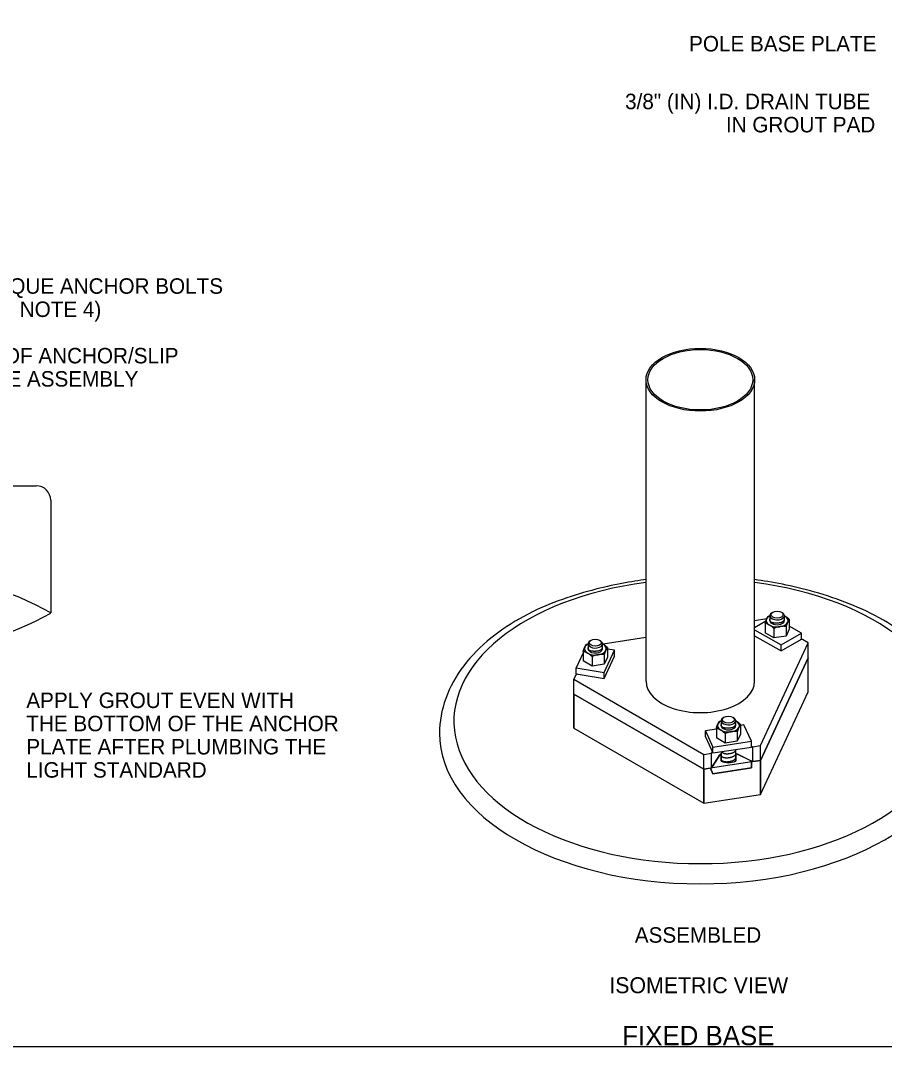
# Model space of a CAD drawing. Extents: x 99862 to 104211, y 98939 to 102076.
# Drawn here: x 101332 to 102226, y 100000 to 101060 of the extents above; entities that cross this region are included whole.
import ezdxf

# ---------------------------------------------------------------- set-up
doc = ezdxf.new("R2010")
doc.units = 0
for name, color, linetype in [('Level 1', 7, 'Continuous'), ('Level 11', 7, 'Continuous'), ('Level 12', 7, 'Continuous'), ('Level 2', 7, 'Continuous'), ('Level 20', 7, 'Continuous'), ('Level 62', 7, 'Continuous'), ('Level 7', 7, 'Continuous'), ('Level 8', 7, 'Continuous'), ('Level 9', 7, 'Continuous')]:
    doc.layers.add(name, color=color, linetype=linetype)

msp = doc.modelspace()

# ---------------------------------------------------------------- linework, layer by layer
at = {"layer": 'Level 1'}
msp.add_lwpolyline([(99862, 99999.5), (103151, 99999.5), (103151, 102075.5), (99862, 102075.5)], close=True, dxfattribs=at)
for centre, start, end in [((101228.7, 100214), 60, 120), ((101228.7, 100681.6), 240, 300)]:
    msp.add_arc(centre, 270, start, end, dxfattribs=at)
at = {"layer": 'Level 11'}
for p, q in [((102103.6, 100439.2), (102092.1, 100432.6)), ((102140.6, 100426.9), (102128, 100434.2)), ((102092.1, 100430.4), (102119.4, 100414.7)), ((102092.1, 100424.3), (102119.4, 100408.6)), ((102119.4, 100414.7), (102140.6, 100426.9)), ((102140.6, 100420.8), (102140.6, 100426.9)), ((102119.4, 100408.6), (102140.6, 100420.8)), ((102119.4, 100408.6), (102119.4, 100414.7)), ((101914.7, 100406.5), (101907.4, 100390.9)), ((101936.4, 100386.4), (101947.1, 100409.4)), ((101936.4, 100380.2), (101947.1, 100403.3)), ((101947.1, 100409.4), (101939.8, 100410.5)), ((101947.1, 100403.3), (101947.1, 100409.4)), ((101907.4, 100384.7), (101907.4, 100390.9)), ((101907.4, 100390.9), (101936.4, 100386.4)), ((101907.4, 100384.7), (101936.4, 100380.2)), ((101936.4, 100380.2), (101936.4, 100386.4)), ((102052.5, 100327.6), (102041.2, 100325.8)), ((102081, 100332), (102077.6, 100331.5)), ((102088.8, 100315.3), (102081, 100332)), ((102041.2, 100319.7), (102041.2, 100325.8)), ((102041.2, 100325.8), (102049, 100309.1)), ((102041.2, 100319.7), (102049, 100303)), ((102049, 100309.1), (102088.8, 100315.3)), ((102049, 100303), (102088.8, 100309.2)), ((102049, 100303), (102049, 100309.1)), ((102088.8, 100309.2), (102088.8, 100315.3))]:
    msp.add_line(p, q, dxfattribs=at)
at = {"layer": 'Level 12'}
for centre, major_axis, start_param, end_param in [((102035.9, 100335.8), (-255, 0), 4.934807, 10.773157), ((102035.9, 100323.6), (-270, 0), 6.283185, 9.424762)]:
    msp.add_ellipse(centre, major_axis=major_axis, ratio=0.57735, start_param=start_param, end_param=end_param, dxfattribs=at)
for points in [[(101979.6, 100482.3), (101965.9, 100480.6), (101925.7, 100473.6), (101852.3, 100448.7), (101784.3, 100397), (101765.9, 100347.3), (101765.9, 100323.6)], [(102305.9, 100323.6), (102305.9, 100345.1), (102289.9, 100392.8), (102227.3, 100444.3), (102152.7, 100472), (102109.3, 100480.1), (102092.1, 100482.3)]]:
    msp.add_open_spline(points, degree=3, dxfattribs=at)
at = {"layer": 'Level 2'}
for p, q in [((102147.5, 100366.3), (102147.5, 100401.5)), ((102147.5, 100366.3), (102147.5, 100401.5)), ((101904.9, 100328.8), (101904.9, 100364)), ((101904.9, 100328.8), (101904.9, 100364)), ((102098.2, 100260.1), (102147.5, 100366.3)), ((101904.9, 100328.8), (102039.6, 100251)), ((102098.2, 100295.3), (102039.6, 100286.2)), ((102054.4, 100298.2), (102047.6, 100287.5)), ((102056.2, 100301), (102054.4, 100298.2)), ((102057.5, 100294.7), (102057.5, 100302.4)), ((102072.5, 100302.6), (102072.5, 100294.7)), ((102088.8, 100293.9), (102088.3, 100295)), ((102098.2, 100260.1), (102098.2, 100295.3)), ((102098.2, 100260.1), (102098.2, 100295.3)), ((102039.6, 100251), (102039.6, 100286.2)), ((102039.6, 100251), (102039.6, 100286.2)), ((102047.6, 100287.5), (102046.3, 100287.3)), ((102046.3, 100287.3), (102049, 100281.6)), ((102049, 100281.6), (102088.8, 100287.7)), ((102088.8, 100287.7), (102088.8, 100293.9)), ((102039.6, 100251), (102098.2, 100260.1))]:
    msp.add_line(p, q, dxfattribs=at)
for points in [[(102098.2, 100260.1), (102147.5, 100366.3), (102147.5, 100401.5), (102098.2, 100295.3), (102098.2, 100260.1)], [(101904.9, 100328.8), (102039.6, 100251), (102039.6, 100286.2), (101904.9, 100364), (101904.9, 100328.8)], [(102046.3, 100287.3), (102039.6, 100286.2), (102039.6, 100251), (102098.2, 100260.1), (102098.2, 100295.3), (102090.2, 100294.1), (102088.3, 100295), (102088.8, 100293.9), (102088.8, 100287.7), (102049, 100281.6), (102046.3, 100287.3)], [(102088.3, 100295), (102075, 100301.4), (102072.5, 100302.6)]]:
    msp.add_lwpolyline(points, dxfattribs=at)
for major_axis, start_param, end_param in [((-9.38, 0), 5.639684, 5.931236), ((10.7, 0), 3.935758, 5.48902)]:
    msp.add_ellipse((102065, 100299.1), major_axis=major_axis, ratio=0.57735, start_param=start_param, end_param=end_param, dxfattribs=at)
at = {"layer": 'Level 62'}
for points, degree in [([(102122.7, 100441.1), (102121.9, 100438.7), (102118.9, 100437.4), (102115.4, 100437.2), (102111, 100437.1), (102107.6, 100438.7), (102107.9, 100441.3)], 4), ([(101934.5, 100412), (101933.7, 100409.6), (101930.7, 100408.2), (101927.2, 100408.1), (101922.8, 100408), (101919.4, 100409.6), (101919.7, 100412.2)], 4), ([(102072.3, 100332.4), (102071.5, 100330.1), (102068.5, 100328.7), (102065, 100328.6), (102060.6, 100328.4), (102057.2, 100330.1), (102057.5, 100332.6)], 4), ([(102072.3, 100305.9), (102071.6, 100304), (102069.5, 100302.7), (102066.8, 100302.2), (102063.2, 100301.6), (102059.5, 100302.3), (102058, 100304.4)], 4), ([(102072.3, 100301.8), (102071.7, 100300), (102069.6, 100298.8), (102067.1, 100298.2), (102061.7, 100297.1), (102057.1, 100298.9), (102057.5, 100302)], 4), ([(102072.3, 100297.7), (102071.7, 100296), (102069.8, 100294.8), (102067.4, 100294.2), (102061.9, 100293), (102057.2, 100294.7), (102057.5, 100297.9)], 4), ([(102057.7, 100294.6), (102057.5, 100295.1), (102057.5, 100295.5), (102057.5, 100295.9)], 3), ([(102071.7, 100294.6), (102071.6, 100294.5), (102071.5, 100294.3), (102071.3, 100294.1)], 3)]:
    msp.add_open_spline(points, degree=degree, dxfattribs=at)
at = {"layer": 'Level 7'}
for p, q in [((102104.6, 100441.6), (102092.1, 100439.7)), ((101979.6, 100422.3), (101935.2, 100415.4)), ((102098.2, 100310.6), (102147.5, 100416.9)), ((102141.6, 100420.2), (102139.2, 100420)), ((102147.5, 100416.9), (102141.6, 100420.2)), ((102147.5, 100401.5), (102147.5, 100416.9)), ((102098.2, 100295.3), (102147.5, 100401.5)), ((101907, 100383.9), (101904.9, 100379.3)), ((101904.9, 100364), (101904.9, 100379.3)), ((101904.9, 100379.3), (102039.6, 100301.5)), ((101909.3, 100384.4), (101907, 100383.9)), ((101904.9, 100364), (102039.6, 100286.2)), ((102088.8, 100310), (102090.2, 100309.4)), ((102090.2, 100309.4), (102098.2, 100310.6)), ((102090.2, 100294.1), (102090.2, 100309.4)), ((102098.2, 100295.3), (102098.2, 100310.6)), ((102039.6, 100301.5), (102047.6, 100302.8)), ((102039.6, 100286.2), (102039.6, 100301.5)), ((102047.6, 100302.8), (102048.4, 100304.1)), ((102047.6, 100287.5), (102047.6, 100302.8)), ((102047.6, 100287.5), (102056.2, 100301)), ((102072.5, 100302.6), (102090.2, 100294.1)), ((102090.2, 100294.1), (102098.2, 100295.3)), ((102039.6, 100286.2), (102047.6, 100287.5))]:
    msp.add_line(p, q, dxfattribs=at)
msp.add_ellipse((102065, 100299.1), major_axis=(-9.38, 0), ratio=0.57735, start_param=5.639684, end_param=5.931236, dxfattribs=at)
at = {"layer": 'Level 8'}
for p, q in [((101979.6, 100689), (101979.6, 100377.2)), ((102092.1, 100377.2), (102092.1, 100689)), ((101172.4, 100579.3), (101348.7, 100579.3)), ((101363.7, 100564.3), (101363.7, 100447.8))]:
    msp.add_line(p, q, dxfattribs=at)
msp.add_arc((101348.7, 100564.3), 15, 0, 90, dxfattribs=at)
for major_axis in [(-56.2, 0), (-54.2, 0)]:
    msp.add_ellipse((102035.9, 100689), major_axis=major_axis, ratio=0.57735, dxfattribs=at)
msp.add_ellipse((102035.9, 100377.2), major_axis=(-56.2, 0), ratio=0.57735, start_param=0, end_param=3.141593, dxfattribs=at)
at = {"layer": 'Level 9'}
for p, q in [((102107.9, 100445), (102107.9, 100439.9)), ((102111.1, 100448.6), (102110.1, 100448.1)), ((102120.7, 100448.1), (102119.8, 100448.6)), ((102122.9, 100439.9), (102122.9, 100445)), ((102102.9, 100437.2), (102102.9, 100427.3)), ((102104.5, 100441.5), (102104.6, 100441.7)), ((102107.7, 100435.2), (102107.3, 100435.5)), ((102118.6, 100433.7), (102118.1, 100433.6)), ((102124.6, 100433.8), (102124.6, 100423.9)), ((102126.4, 100438.4), (102126.2, 100438.1)), ((102128, 100441.1), (102128, 100431.2)), ((102112.1, 100422), (102102.9, 100427.3)), ((102112.1, 100431.9), (102112.1, 100422)), ((102124.6, 100423.9), (102112.1, 100422)), ((102128, 100431.2), (102124.6, 100423.9)), ((101916.3, 100412.4), (101916.4, 100412.6)), ((101919.7, 100415.9), (101919.7, 100410.8)), ((101922.9, 100419.5), (101921.9, 100418.9)), ((101932.5, 100418.9), (101931.6, 100419.5)), ((101934.7, 100410.8), (101934.7, 100415.9)), ((101939.8, 100412), (101939.8, 100402.1)), ((101914.7, 100408.1), (101914.7, 100398.2)), ((101919.5, 100406.1), (101919.1, 100406.4)), ((101923.9, 100402.8), (101923.9, 100392.9)), ((101930.4, 100404.6), (101929.8, 100404.5)), ((101936.4, 100404.7), (101936.4, 100394.8)), ((101939.8, 100402.1), (101936.4, 100394.8)), ((101938.1, 100409.3), (101938, 100409)), ((101923.9, 100392.9), (101914.7, 100398.2)), ((101936.4, 100394.8), (101923.9, 100392.9)), ((102060.6, 100339.9), (102059.7, 100339.4)), ((102070.3, 100339.4), (102069.4, 100339.9)), ((102052.5, 100328.5), (102052.5, 100318.6)), ((102054.1, 100332.9), (102054.2, 100333)), ((102057.3, 100326.6), (102056.9, 100326.8)), ((102057.5, 100336.3), (102057.5, 100331.3)), ((102072.5, 100331.3), (102072.5, 100336.3)), ((102075.9, 100329.7), (102075.8, 100329.5)), ((102077.6, 100332.4), (102077.6, 100322.5)), ((102061.6, 100313.3), (102052.5, 100318.6)), ((102061.6, 100323.2), (102061.6, 100313.3)), ((102068.2, 100325.1), (102067.6, 100325)), ((102074.2, 100325.2), (102074.2, 100315.3)), ((102077.6, 100322.5), (102074.2, 100315.3)), ((102074.2, 100315.3), (102061.6, 100313.3)), ((102072.5, 100294.7), (102072.5, 100306.6)), ((102057.5, 100304.3), (102057.5, 100294.7)), ((102072.5, 100294.7), (102072.5, 100294.7))]:
    msp.add_line(p, q, dxfattribs=at)
for centre, major_axis, start_param, end_param in [((102115.4, 100439.9), (-11.3, 0), 5.442115, 6.008202), ((102115.4, 100445), (-7.5, 0), 5.497787, 9.424778), ((102115.4, 100445), (-7.5, 0), 3.141593, 3.926991), ((102115.4, 100439.9), (-11.3, 0), 3.926991, 3.982662), ((102115.4, 100439.9), (-11.3, 0), 2.900683, 3.926991), ((102115.4, 100439.9), (-11.3, 0), 6.034615, 7.043856), ((102115.4, 100439.9), (-11.3, 0), 0.810125, 1.805354), ((102115.4, 100439.9), (7.5, 0), 3.141411, 6.283185), ((102115.4, 100439.9), (-11.3, 0), 1.859837, 2.858903), ((101927.2, 100410.8), (-11.3, 0), 6.034615, 7.043856), ((101927.2, 100410.8), (-11.3, 0), 5.442115, 6.008202), ((101927.2, 100415.9), (-7.5, 0), 5.49774, 9.424778), ((101927.2, 100415.9), (-7.5, 0), 3.141593, 3.927038), ((101927.2, 100410.8), (-11.3, 0), 3.926991, 3.982662), ((101927.2, 100410.8), (-11.3, 0), 2.900683, 3.926991), ((101927.2, 100410.8), (-11.3, 0), 0.810125, 1.805354), ((101927.2, 100410.8), (7.5, 0), 3.141414, 6.283185), ((101927.2, 100410.8), (-11.3, 0), 1.859837, 2.858903), ((102065, 100336.3), (-7.5, 0), 5.497787, 9.424778), ((102065, 100336.3), (-7.5, 0), 3.141593, 3.926991), ((102065, 100331.3), (-11.3, 0), 6.034615, 7.043856), ((102065, 100331.3), (-11.3, 0), 5.442115, 6.008202), ((102065, 100331.3), (-11.3, 0), 0.810125, 1.805354), ((102065, 100331.3), (7.5, 0), 3.141408, 6.283185), ((102065, 100331.3), (-11.3, 0), 1.859837, 2.858903), ((102065, 100331.3), (-11.3, 0), 3.926991, 3.982662), ((102065, 100331.3), (-11.3, 0), 2.900683, 3.926991), ((102065, 100299.1), (10.7, 0), 3.935758, 5.48902)]:
    msp.add_ellipse(centre, major_axis=major_axis, ratio=0.57735, start_param=start_param, end_param=end_param, dxfattribs=at)
for centre in [(102115.4, 100446.1), (101927.2, 100417), (102065, 100337.4)]:
    msp.add_ellipse(centre, major_axis=(-6.17, 0), ratio=0.57735, dxfattribs=at)
for points, degree in [([(102104.6, 100441.7), (102105.2, 100442.9), (102105.7, 100443.8), (102106.3, 100444.4)], 2), ([(102106.3, 100444.4), (102106.8, 100444.7), (102107.4, 100444.9), (102107.9, 100445.1)], 2), ([(102123.4, 100444.5), (102123.2, 100444.6), (102123.1, 100444.7), (102122.9, 100444.8)], 2), ([(102128, 100441.1), (102126.5, 100442.4), (102124.9, 100443.6), (102123.4, 100444.5)], 2), ([(102102.9, 100437.2), (102103.4, 100438.8), (102104, 100440.3), (102104.5, 100441.5)], 2), ([(102107.3, 100435.5), (102106.5, 100435.9), (102105.8, 100436.2), (102104.3, 100436.8), (102103.6, 100437), (102102.9, 100437.2)], 3), ([(102112.1, 100431.9), (102110.6, 100433.2), (102109.2, 100434.4), (102107.7, 100435.2)], 2), ([(102118.1, 100433.6), (102116, 100433.3), (102114, 100432.7), (102112.1, 100431.9)], 2), ([(102124.6, 100433.8), (102122.7, 100434), (102120.7, 100434), (102118.6, 100433.7)], 2), ([(102126.2, 100438.1), (102125.7, 100436.9), (102125.2, 100435.5), (102124.6, 100433.8)], 2), ([(102128, 100441.1), (102127.5, 100440.4), (102126.9, 100439.6), (102126.4, 100438.4)], 2), ([(101914.7, 100408.1), (101915.2, 100409.7), (101915.8, 100411.2), (101916.3, 100412.4)], 2), ([(101916.4, 100412.6), (101917, 100413.8), (101917.5, 100414.6), (101918, 100415.3)], 2), ([(101918, 100415.3), (101918.6, 100415.5), (101919.2, 100415.7), (101919.7, 100415.9)], 2), ([(101935.2, 100415.4), (101935, 100415.5), (101934.9, 100415.6), (101934.7, 100415.7)], 2), ([(101939.8, 100412), (101938.3, 100413.3), (101936.7, 100414.5), (101935.2, 100415.4)], 2), ([(101939.8, 100412), (101939.2, 100411.3), (101938.7, 100410.5), (101938.1, 100409.3)], 2), ([(101919.1, 100406.4), (101918.3, 100406.8), (101917.6, 100407.1), (101916.1, 100407.7), (101915.4, 100407.9), (101914.7, 100408.1)], 3), ([(101923.9, 100402.8), (101922.4, 100404.1), (101921, 100405.2), (101919.5, 100406.1)], 2), ([(101929.8, 100404.5), (101927.8, 100404.2), (101925.8, 100403.6), (101923.9, 100402.8)], 2), ([(101936.4, 100404.7), (101934.4, 100404.9), (101932.5, 100404.9), (101930.4, 100404.6)], 2), ([(101938, 100409), (101937.5, 100407.8), (101936.9, 100406.3), (101936.4, 100404.7)], 2), ([(102052.5, 100328.5), (102053, 100330.2), (102053.5, 100331.7), (102054.1, 100332.9)], 2), ([(102056.9, 100326.8), (102056.1, 100327.2), (102055.4, 100327.6), (102053.9, 100328.1), (102053.2, 100328.4), (102052.5, 100328.5)], 3), ([(102054.2, 100333), (102054.7, 100334.2), (102055.3, 100335.1), (102055.8, 100335.8)], 2), ([(102055.8, 100335.8), (102056.4, 100336), (102056.9, 100336.2), (102057.5, 100336.4)], 2), ([(102061.6, 100323.2), (102060.2, 100324.5), (102058.7, 100325.7), (102057.3, 100326.6)], 2), ([(102073, 100335.9), (102072.8, 100336), (102072.7, 100336), (102072.5, 100336.1)], 2), ([(102077.6, 100332.4), (102076.1, 100333.8), (102074.5, 100335), (102073, 100335.9)], 2), ([(102075.8, 100329.5), (102075.3, 100328.3), (102074.7, 100326.8), (102074.2, 100325.2)], 2), ([(102077.6, 100332.4), (102077, 100331.7), (102076.5, 100330.9), (102075.9, 100329.7)], 2), ([(102067.6, 100325), (102065.6, 100324.6), (102063.6, 100324), (102061.6, 100323.2)], 2), ([(102074.2, 100325.2), (102072.2, 100325.3), (102070.2, 100325.3), (102068.2, 100325.1)], 2)]:
    msp.add_open_spline(points, degree=degree, dxfattribs=at)

# ---------------------------------------------------------------- texts
at = {"layer": 'Level 12'}
msp.add_text('FIXED BASE', height=20, dxfattribs=at).set_placement((101955.1, 100000.8))
at = {"layer": 'Level 20'}
for s, height, p in [('POLE BASE PLATE', 16, (102024.3, 101028.5)), (' 3/8" (IN) I.D. DRAIN TUBE', 16, (101952.1, 100968.8)), ('IN GROUT PAD', 16, (102062.4, 100944.8)), ('TORQUE ANCHOR BOLTS', 16, (101275.7, 100777.9)), ('(SEE NOTE 4)', 16, (101275.7, 100753.9)), ('TOP OF ANCHOR/SLIP', 16, (101265.3, 100705.9)), ('PLATE ASSEMBLY', 16, (101265.3, 100681.9)), ('APPLY GROUT EVEN WITH', 16, (101338.4, 100349.5)), ('THE BOTTOM OF THE ANCHOR ', 16, (101338.4, 100325.5)), ('PLATE AFTER PLUMBING THE ', 16, (101338.4, 100301.5)), ('LIGHT STANDARD', 16, (101338.4, 100277.5)), ('ASSEMBLED', 16, (101968.1, 100106.8)), ('ISOMETRIC VIEW', 16.5, (101941.7, 100054.6))]:
    msp.add_text(s, height=height, dxfattribs=at).set_placement(p)

doc.saveas('drawing.dxf')
